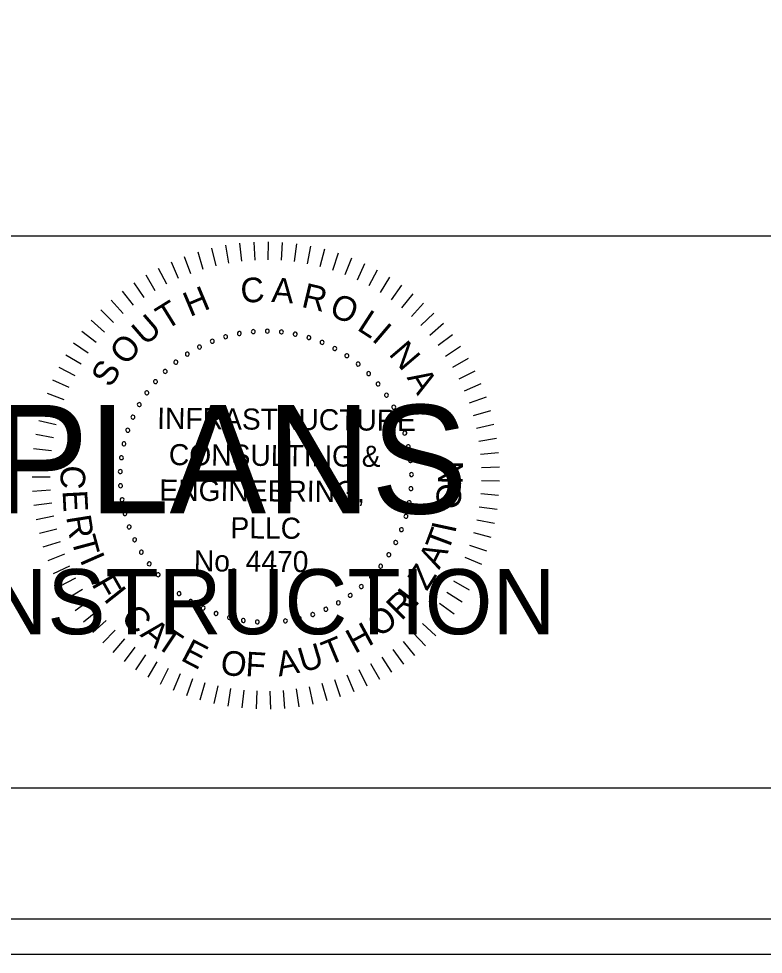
# Model space of a CAD drawing. Extents: x 967 to 1746, y 964 to 7904.
# Drawn here: x 1189.3 to 1212.88, y 7123.72 to 7153.36 of the extents above; entities that cross this region are included whole.
import ezdxf

# ---------------------------------------------------------------- set-up
doc = ezdxf.new("R2010")
doc.units = 0
for name, color, linetype in [('RD_SHT_Bndy', 7, 'Continuous'), ('RD_SHT_IplotShp', 7, 'Continuous'), ('RD_SHT_Misc1', 7, 'Continuous'), ('RD_SHT_Misc2', 7, 'Continuous'), ('RD_Sketch1', 7, 'Continuous')]:
    doc.layers.add(name, color=color, linetype=linetype)

msp = doc.modelspace()

# ---------------------------------------------------------------- linework, layer by layer
at = {"layer": 'RD_SHT_Bndy'}
for p, q in [((996.114, 7146.486), (1323.886, 7146.486)), ((1323.886, 7128.983), (996.114, 7128.983))]:
    msp.add_line(p, q, dxfattribs=at)
at = {"layer": 'RD_SHT_IplotShp'}
for points in [[(967.409, 7123.72), (1326.285, 7123.72), (1326.285, 7343.72), (967.409, 7343.72)], [(988.525, 7124.84), (1326.285, 7124.84), (1326.285, 7342.6), (988.525, 7342.6)]]:
    msp.add_lwpolyline(points, close=True, dxfattribs=at)
at = {"layer": 'RD_SHT_Misc1'}
for p, q in [((1195.846, 7146.181), (1195.945, 7145.62)), ((1196.292, 7146.245), (1196.357, 7145.68)), ((1196.742, 7146.282), (1196.772, 7145.714)), ((1197.194, 7146.292), (1197.189, 7145.723)), ((1197.645, 7146.274), (1197.606, 7145.706)), ((1198.094, 7146.228), (1198.02, 7145.664)), ((1198.54, 7146.156), (1198.432, 7145.596)), ((1194.968, 7145.971), (1195.134, 7145.427)), ((1195.403, 7146.09), (1195.536, 7145.536)), ((1198.98, 7146.056), (1198.838, 7145.504)), ((1199.414, 7145.929), (1199.238, 7145.387)), ((1194.122, 7145.656), (1194.353, 7145.136)), ((1194.54, 7145.827), (1194.739, 7145.293)), ((1199.839, 7145.777), (1199.63, 7145.246)), ((1200.253, 7145.598), (1200.013, 7145.082)), ((1193.715, 7145.461), (1193.978, 7144.956)), ((1200.656, 7145.395), (1200.385, 7144.894)), ((1192.94, 7144.997), (1193.263, 7144.528)), ((1193.321, 7145.241), (1193.614, 7144.752)), ((1201.047, 7145.167), (1200.745, 7144.684)), ((1192.576, 7144.731), (1192.926, 7144.282)), ((1201.422, 7144.917), (1201.092, 7144.453)), ((1192.228, 7144.443), (1192.605, 7144.016)), ((1201.781, 7144.643), (1201.424, 7144.2)), ((1191.899, 7144.134), (1192.301, 7143.731)), ((1202.124, 7144.349), (1201.739, 7143.928)), ((1191.589, 7143.805), (1192.015, 7143.428)), ((1202.447, 7144.034), (1202.038, 7143.638)), ((1202.751, 7143.7), (1202.318, 7143.329)), ((1191.299, 7143.459), (1191.748, 7143.108)), ((1203.034, 7143.348), (1202.579, 7143.004)), ((1191.032, 7143.095), (1191.501, 7142.772)), ((1203.294, 7142.979), (1202.82, 7142.664)), ((1190.787, 7142.716), (1191.274, 7142.422)), ((1203.532, 7142.595), (1203.04, 7142.31)), ((1190.565, 7142.323), (1191.07, 7142.059)), ((1203.746, 7142.198), (1203.237, 7141.943)), ((1190.368, 7141.916), (1190.888, 7141.684)), ((1203.936, 7141.788), (1203.412, 7141.564)), ((1190.196, 7141.499), (1190.729, 7141.299)), ((1204.1, 7141.367), (1203.563, 7141.176)), ((1190.05, 7141.072), (1190.594, 7140.905)), ((1204.238, 7140.937), (1203.691, 7140.779)), ((1189.93, 7140.636), (1190.484, 7140.503)), ((1204.349, 7140.5), (1203.794, 7140.375)), ((1189.837, 7140.195), (1190.398, 7140.095)), ((1204.434, 7140.056), (1203.872, 7139.966)), ((1189.771, 7139.748), (1190.337, 7139.683)), ((1204.491, 7139.608), (1203.925, 7139.552)), ((1189.732, 7139.298), (1190.301, 7139.267)), ((1204.522, 7139.158), (1203.953, 7139.137)), ((1189.721, 7138.847), (1190.29, 7138.851)), ((1204.524, 7138.706), (1203.955, 7138.72)), ((1189.737, 7138.396), (1190.306, 7138.434)), ((1204.499, 7138.256), (1203.932, 7138.304)), ((1189.781, 7137.946), (1190.346, 7138.019)), ((1204.447, 7137.807), (1203.884, 7137.89)), ((1189.852, 7137.5), (1190.412, 7137.608)), ((1204.367, 7137.363), (1203.81, 7137.479)), ((1189.951, 7137.06), (1190.502, 7137.201)), ((1204.261, 7136.924), (1203.712, 7137.074)), ((1190.076, 7136.626), (1190.617, 7136.8)), ((1204.128, 7136.492), (1203.589, 7136.676)), ((1190.227, 7136.2), (1190.757, 7136.408)), ((1203.969, 7136.07), (1203.442, 7136.286)), ((1190.403, 7135.785), (1190.92, 7136.024)), ((1203.784, 7135.658), (1203.271, 7135.906)), ((1190.605, 7135.381), (1191.106, 7135.651)), ((1203.574, 7135.258), (1203.078, 7135.537)), ((1190.831, 7134.99), (1191.315, 7135.291)), ((1203.341, 7134.871), (1202.862, 7135.18)), ((1191.081, 7134.614), (1191.545, 7134.943)), ((1191.353, 7134.253), (1191.796, 7134.61)), ((1203.085, 7134.5), (1202.626, 7134.837)), ((1191.646, 7133.91), (1192.067, 7134.293)), ((1202.806, 7134.145), (1202.368, 7134.509)), ((1191.96, 7133.585), (1192.356, 7133.994)), ((1202.506, 7133.807), (1202.092, 7134.197)), ((1192.293, 7133.28), (1192.664, 7133.712)), ((1202.186, 7133.488), (1201.796, 7133.903)), ((1192.644, 7132.996), (1192.988, 7133.45)), ((1201.847, 7133.19), (1201.484, 7133.628)), ((1193.011, 7132.734), (1193.327, 7133.208)), ((1201.119, 7132.657), (1200.811, 7133.136)), ((1201.491, 7132.912), (1201.155, 7133.372)), ((1193.394, 7132.495), (1193.68, 7132.987)), ((1200.731, 7132.425), (1200.453, 7132.922)), ((1193.791, 7132.279), (1194.047, 7132.788)), ((1194.2, 7132.088), (1194.424, 7132.612)), ((1199.918, 7132.034), (1199.702, 7132.561)), ((1200.331, 7132.217), (1200.083, 7132.73)), ((1194.62, 7131.923), (1194.812, 7132.459)), ((1195.05, 7131.783), (1195.208, 7132.33)), ((1195.487, 7131.67), (1195.612, 7132.225)), ((1199.063, 7131.745), (1198.913, 7132.295)), ((1199.495, 7131.877), (1199.312, 7132.416)), ((1195.93, 7131.584), (1196.021, 7132.146)), ((1196.377, 7131.524), (1196.434, 7132.091)), ((1196.828, 7131.493), (1196.85, 7132.062)), ((1197.279, 7131.488), (1197.267, 7132.058)), ((1197.73, 7131.512), (1197.683, 7132.079)), ((1198.179, 7131.562), (1198.097, 7132.126)), ((1198.624, 7131.64), (1198.508, 7132.198))]:
    msp.add_line(p, q, dxfattribs=at)
for centre, start, end in [((1196.727, 7143.447), 5.0653, 185.0653), ((1197.172, 7143.464), 359.5268, 179.5268), ((1197.617, 7143.438), 353.9884, 173.9884), ((1195.429, 7143.142), 21.6807, 201.6807), ((1195.851, 7143.285), 16.1422, 196.1422), ((1195.851, 7143.285), 196.1422, 16.1422), ((1196.285, 7143.388), 10.6038, 190.6038), ((1196.285, 7143.388), 190.6038, 10.6038), ((1196.727, 7143.447), 185.0653, 5.0653), ((1197.172, 7143.464), 179.5268, 359.5268), ((1197.617, 7143.438), 173.9884, 353.9884), ((1198.057, 7143.369), 168.4499, 348.4499), ((1198.057, 7143.369), 348.4499, 168.4499), ((1198.489, 7143.258), 162.9114, 342.9114), ((1198.489, 7143.258), 342.9114, 162.9114), ((1195.023, 7142.958), 27.2191, 207.2191), ((1195.023, 7142.958), 207.2191, 27.2191), ((1195.429, 7143.142), 201.6807, 21.6807), ((1198.908, 7143.106), 157.373, 337.373), ((1198.908, 7143.106), 337.373, 157.373), ((1199.31, 7142.914), 151.8345, 331.8345), ((1199.31, 7142.914), 331.8345, 151.8345), ((1194.637, 7142.736), 32.7576, 212.7576), ((1194.637, 7142.736), 212.7576, 32.7576), ((1199.692, 7142.684), 146.2961, 326.2961), ((1199.692, 7142.684), 326.2961, 146.2961), ((1194.274, 7142.478), 38.2961, 218.2961), ((1194.274, 7142.478), 218.2961, 38.2961), ((1200.05, 7142.419), 140.7576, 320.7576), ((1200.05, 7142.419), 320.7576, 140.7576), ((1193.937, 7142.186), 43.8345, 223.8345), ((1193.937, 7142.186), 223.8345, 43.8345), ((1200.38, 7142.12), 135.2191, 315.2191), ((1200.38, 7142.12), 315.2191, 135.2191), ((1193.63, 7141.862), 49.373, 229.373), ((1193.63, 7141.862), 229.373, 49.373), ((1200.68, 7141.79), 129.6807, 309.6807), ((1200.68, 7141.79), 309.6807, 129.6807), ((1193.356, 7141.511), 54.9114, 234.9114), ((1193.356, 7141.511), 234.9114, 54.9114), ((1200.947, 7141.433), 124.1422, 304.1422), ((1200.947, 7141.433), 304.1422, 124.1422), ((1193.117, 7141.135), 60.4499, 240.4499), ((1193.117, 7141.135), 240.4499, 60.4499), ((1201.179, 7141.052), 118.6038, 298.6038), ((1201.179, 7141.052), 298.6038, 118.6038), ((1192.915, 7140.737), 65.9884, 245.9884), ((1192.915, 7140.737), 245.9884, 65.9884), ((1201.372, 7140.651), 113.0653, 293.0653), ((1201.372, 7140.651), 293.0653, 113.0653), ((1192.753, 7140.322), 71.5268, 251.5268), ((1192.753, 7140.322), 251.5268, 71.5268), ((1201.526, 7140.233), 107.5268, 287.5268), ((1201.526, 7140.233), 287.5268, 107.5268), ((1192.632, 7139.894), 77.0653, 257.0653), ((1192.632, 7139.894), 257.0653, 77.0653), ((1201.638, 7139.801), 101.9884, 281.9884), ((1201.638, 7139.801), 281.9884, 101.9884), ((1192.552, 7139.455), 82.6038, 262.6038), ((1192.552, 7139.455), 262.6038, 82.6038), ((1201.709, 7139.361), 96.4499, 276.4499), ((1201.709, 7139.361), 276.4499, 96.4499), ((1192.515, 7139.011), 88.1422, 268.1422), ((1192.515, 7139.011), 268.1422, 88.1422), ((1201.737, 7138.917), 90.9114, 270.9114), ((1201.737, 7138.917), 270.9114, 90.9114), ((1192.522, 7138.565), 93.6807, 273.6807), ((1192.522, 7138.565), 273.6807, 93.6807), ((1201.721, 7138.471), 85.373, 265.373), ((1201.721, 7138.471), 265.373, 85.373), ((1192.571, 7138.122), 99.2191, 279.2191), ((1192.571, 7138.122), 279.2191, 99.2191), ((1201.663, 7138.029), 79.8345, 259.8345), ((1201.663, 7138.029), 259.8345, 79.8345), ((1192.662, 7137.686), 104.7576, 284.7576), ((1192.662, 7137.686), 284.7576, 104.7576), ((1201.563, 7137.595), 74.2961, 254.2961), ((1201.563, 7137.595), 254.2961, 74.2961), ((1192.796, 7137.261), 110.2961, 290.2961), ((1192.796, 7137.261), 290.2961, 110.2961), ((1201.42, 7137.173), 68.7576, 248.7576), ((1201.42, 7137.173), 248.7576, 68.7576), ((1192.97, 7136.851), 115.8345, 295.8345), ((1192.97, 7136.851), 295.8345, 115.8345), ((1201.238, 7136.766), 63.2191, 243.2191), ((1201.238, 7136.766), 243.2191, 63.2191), ((1193.182, 7136.459), 121.373, 301.373), ((1193.182, 7136.459), 301.373, 121.373), ((1201.018, 7136.379), 57.6807, 237.6807), ((1201.018, 7136.379), 237.6807, 57.6807), ((1193.432, 7136.09), 126.9114, 306.9114), ((1193.432, 7136.09), 306.9114, 126.9114), ((1200.761, 7136.014), 52.1422, 232.1422), ((1193.715, 7135.746), 132.4499, 312.4499), ((1193.715, 7135.746), 312.4499, 132.4499), ((1200.761, 7136.014), 232.1422, 52.1422), ((1194.031, 7135.431), 317.9884, 137.9884), ((1200.47, 7135.677), 46.6038, 226.6038), ((1200.47, 7135.677), 226.6038, 46.6038), ((1194.031, 7135.431), 137.9884, 317.9884), ((1194.376, 7135.149), 143.5268, 323.5268), ((1194.376, 7135.149), 323.5268, 143.5268), ((1200.148, 7135.369), 41.0653, 221.0653), ((1200.148, 7135.369), 221.0653, 41.0653), ((1194.746, 7134.901), 149.0653, 329.0653), ((1194.746, 7134.901), 329.0653, 149.0653), ((1199.422, 7134.853), 29.9884, 209.9884), ((1199.422, 7134.853), 209.9884, 29.9884), ((1199.798, 7135.093), 35.5268, 215.5268), ((1199.798, 7135.093), 215.5268, 35.5268), ((1195.139, 7134.69), 154.6038, 334.6038), ((1195.139, 7134.69), 334.6038, 154.6038), ((1199.026, 7134.65), 24.4499, 204.4499), ((1199.026, 7134.65), 204.4499, 24.4499), ((1195.55, 7134.517), 160.1422, 340.1422), ((1195.55, 7134.517), 340.1422, 160.1422), ((1195.975, 7134.386), 165.6807, 345.6807), ((1195.975, 7134.386), 345.6807, 165.6807), ((1196.412, 7134.295), 171.2191, 351.2191), ((1196.412, 7134.295), 351.2191, 171.2191), ((1196.855, 7134.248), 356.7576, 176.7576), ((1197.301, 7134.243), 2.2961, 182.2961), ((1197.745, 7134.282), 7.8345, 187.8345), ((1197.745, 7134.282), 187.8345, 7.8345), ((1198.183, 7134.363), 13.373, 193.373), ((1198.183, 7134.363), 193.373, 13.373), ((1198.611, 7134.486), 18.9114, 198.9114), ((1198.611, 7134.486), 198.9114, 18.9114), ((1196.855, 7134.248), 176.7576, 356.7576), ((1197.301, 7134.243), 182.2961, 2.2961)]:
    msp.add_arc(centre, 0.0627, start, end, dxfattribs=at)
at = {"layer": 'RD_Sketch1'}
msp.add_lwpolyline([(967.409, 7123.72), (1326.285, 7123.72), (1326.285, 7343.72), (967.409, 7343.72)], close=True, dxfattribs=at)

# ---------------------------------------------------------------- texts
at = {"layer": 'RD_SHT_Misc1'}
for s, height, rotation, p in [('C', 0.78, 4.7281, (1196.355, 7144.346)), ('A', 0.78, 355.6981, (1197.29, 7144.39)), ('R', 0.78, 346.6681, (1198.222, 7144.238)), ('H', 0.78, 22.7882, (1194.72, 7143.904)), ('T', 0.78, 31.8182, (1193.961, 7143.478)), ('O', 0.78, 337.638, (1199.096, 7143.972)), ('L', 0.78, 327.108, (1199.981, 7143.52)), ('U', 0.78, 40.8482, (1193.306, 7142.976)), ('I', 0.78, 319.578, (1200.451, 7143.182)), ('O', 0.78, 49.8782, (1192.707, 7142.341)), ('N', 0.78, 310.548, (1200.994, 7142.728)), ('S', 0.78, 58.9083, (1192.211, 7141.642)), ('A', 0.78, 301.5179, (1201.576, 7141.991)), ('INFRASTRUCTURE', 0.66873, 359.5268, (1193.682, 7140.367)), ('CONSULTING &', 0.66873, 359.5268, (1194.051, 7139.217)), ('C', 0.78, 267.025, (1190.646, 7139.227)), ('N', 0.78, 89.2085, (1203.359, 7138.604)), ('ENGINEERING,', 0.66873, 359.5268, (1193.751, 7138.095)), ('O', 0.78, 83.2085, (1203.26, 7137.786)), ('E', 0.78, 273.025, (1190.685, 7138.408)), ('R', 0.78, 279.025, (1190.799, 7137.583)), ('PLLC', 0.6687, 359.5268, (1196.002, 7136.9)), ('T', 0.78, 69.3954, (1202.891, 7136.428)), ('I', 0.78, 77.9093, (1203.121, 7137.032)), ('T', 0.78, 285.025, (1190.955, 7136.878)), ('I', 0.78, 293.7713, (1191.221, 7136.225)), ('No. 4470', 0.6687, 359.5268, (1194.843, 7135.855)), ('A', 0.78, 63.3954, (1202.616, 7135.888)), ('Z', 0.78, 57.3954, (1202.224, 7135.206)), ('F', 0.78, 299.7713, (1191.589, 7135.455)), ('I', 0.78, 308.5268, (1191.965, 7134.973)), ('R', 0.78, 44.5268, (1201.415, 7134.267)), ('I', 0.78, 52.3339, (1201.856, 7134.69)), ('C', 0.78, 314.5268, (1192.496, 7134.346)), ('O', 0.78, 38.5268, (1200.73, 7133.731)), ('A', 0.78, 320.5268, (1193.115, 7133.822)), ('T', 0.78, 326.5268, (1193.602, 7133.478)), ('H', 0.78, 28.5268, (1199.942, 7133.23)), ('E', 0.78, 332.5268, (1194.394, 7133.051)), ('T', 0.78, 22.5268, (1199.108, 7132.856)), ('U', 0.78, 16.5268, (1198.288, 7132.638)), ('O', 0.78, 350.5268, (1195.647, 7132.614)), ('F', 0.78, 356.5268, (1196.465, 7132.532)), ('A', 0.78, 10.5268, (1197.537, 7132.517))]:
    msp.add_text(s, height=height, rotation=rotation, dxfattribs=at).set_placement(p)
at = {"layer": 'RD_SHT_Misc2'}
for s, height, p in [('FINAL PLANS', 3.4375, (1174.145, 7137.685)), ('NOT FOR CONSTRUCTION', 2.0625, (1170.901, 7133.86))]:
    msp.add_text(s, height=height, dxfattribs=at).set_placement(p)

doc.saveas('drawing.dxf')
